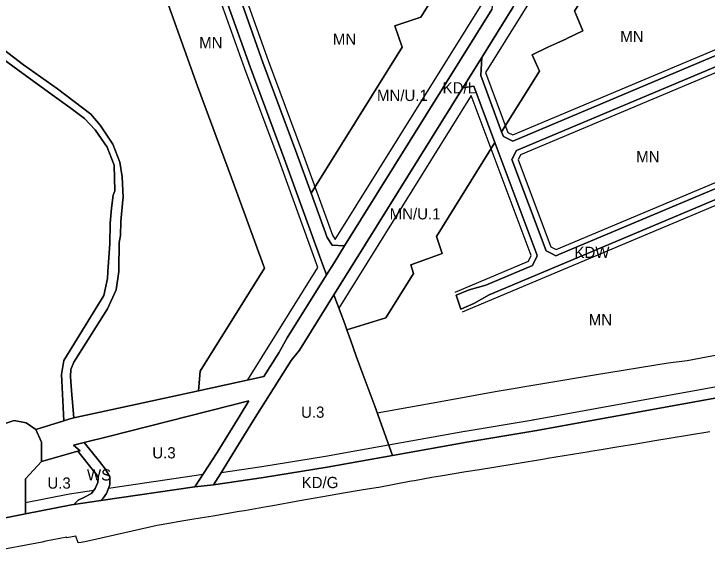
# Model space of a CAD drawing. Extents: x 7438199 to 7440548, y 5549253 to 5551017.
# Drawn here: x 7439598 to 7440215, y 5549324 to 5549804 of the extents above; entities that cross this region are included whole.
import ezdxf

# ---------------------------------------------------------------- set-up
doc = ezdxf.new("R2010")
doc.units = 0
for name, color, linetype in [('linie_rozgraniczajace', 7, 'Continuous'), ('linie_zabudowy_nieprzekraczalne', 7, 'Continuous'), ('oznaczenia_przeznaczen', 7, 'Continuous')]:
    doc.layers.add(name, color=color, linetype=linetype)

msp = doc.modelspace()

# ---------------------------------------------------------------- linework, layer by layer
at = {"layer": 'linie_rozgraniczajace'}
for points in [[(7440227.08, 5550005.17), (7440213.47, 5550001.07), (7440202.09, 5549996.27), (7440206.12, 5549984.95), (7440122.18, 5549849.49), (7440120.23, 5549848.95), (7440108.63, 5549844.06), (7440113.1, 5549832.93), (7440096.64, 5549806.47), (7440097.49, 5549804.44), (7440104.04, 5549788.87), (7440090.03, 5549782.03), (7440089.49, 5549781.67), (7440080.98, 5549777.82), (7440073.14, 5549774.28), (7440059.1, 5549767.45), (7440065.46, 5549752.89), (7440031.9, 5549698.99), (7440013.26, 5549748.91), (7440014.17, 5549765.09), (7440041.95, 5549809.72), (7440239.68, 5550128.82)], [(7439763.48, 5549881.63), (7439807.99, 5549756.65), (7439838.39, 5549675.06), (7439872.18, 5549581.79), (7439875.93, 5549571.43), (7439840.95, 5549515.24), (7439833.42, 5549501.96), (7439820.29, 5549480.94), (7439762.06, 5549468.22), (7439763.53, 5549485.48), (7439820.65, 5549577.24), (7439819.77, 5549579.67), (7439791.46, 5549657.81), (7439761.02, 5549739.54), (7439716.26, 5549865.2)], [(7439801.04, 5549811.94), (7439819.27, 5549760.76), (7439849.66, 5549679.19), (7439862.34, 5549644.19), (7439876.67, 5549604.63), (7439881.11, 5549597.9), (7439892.09, 5549597.4), (7439882.65, 5549582.22), (7439875.93, 5549571.43), (7439872.18, 5549581.79), (7439838.39, 5549675.06), (7439807.99, 5549756.65), (7439763.48, 5549881.63)], [(7439716.26, 5549865.2), (7439761.02, 5549739.54), (7439791.46, 5549657.81), (7439819.77, 5549579.67), (7439820.65, 5549577.24), (7439763.53, 5549485.48), (7439762.06, 5549468.22), (7439712.84, 5549457.46), (7439651.11, 5549443.98), (7439649.06, 5549468.02), (7439647.96, 5549480.76), (7439648.28, 5549487.18), (7439651.04, 5549493.78), (7439681.14, 5549541.18), (7439688.8, 5549557.97), (7439690.97, 5549574.44), (7439691.18, 5549576.06), (7439691.29, 5549600.29), (7439692.47, 5549606.39), (7439692.73, 5549619.01), (7439694.66, 5549638.27), (7439694.87, 5549640.3), (7439694.01, 5549658.77), (7439691.96, 5549671.97), (7439685.83, 5549687.74), (7439674.5, 5549704.91), (7439666.08, 5549714.5), (7439636.39, 5549737.26), (7439606.18, 5549758.61), (7439574.15, 5549782.83)], [(7440041.95, 5549809.72), (7440014.17, 5549765.09), (7439997.34, 5549738.06), (7439900.77, 5549582.95), (7439882.54, 5549553.67), (7439851.78, 5549504.26), (7439844.39, 5549495.21), (7439818.18, 5549453.4), (7439811.01, 5549441.98), (7439797.53, 5549420.26), (7439781.66, 5549394.3), (7439775.48, 5549384.28), (7439758.88, 5549382.65), (7439778.73, 5549413.02), (7439799.07, 5549446.3), (7439806.9, 5549459.11), (7439681.83, 5549427.53), (7439660.17, 5549422.14), (7439650.59, 5549419.75), (7439656.54, 5549414.79), (7439654.49, 5549414.36), (7439622.38, 5549405.09), (7439622.1, 5549422.44), (7439617.25, 5549433.53), (7439642.01, 5549441.52), (7439646.47, 5549442.96), (7439651.11, 5549443.98), (7439712.84, 5549457.46), (7439762.06, 5549468.22), (7439820.29, 5549480.94), (7439833.42, 5549501.96), (7439840.95, 5549515.24), (7439875.93, 5549571.43), (7439882.65, 5549582.22), (7439892.09, 5549597.4), (7440023.05, 5549807.75)], [(7439574.15, 5549782.83), (7439606.18, 5549758.61), (7439636.39, 5549737.26), (7439666.08, 5549714.5), (7439674.5, 5549704.91), (7439685.83, 5549687.74), (7439691.96, 5549671.97), (7439694.01, 5549658.77), (7439694.87, 5549640.3), (7439694.66, 5549638.27), (7439692.73, 5549619.01), (7439692.47, 5549606.39), (7439691.29, 5549600.29), (7439691.18, 5549576.06), (7439690.97, 5549574.44), (7439688.8, 5549557.97), (7439681.14, 5549541.18), (7439651.04, 5549493.78), (7439648.28, 5549487.18), (7439647.96, 5549480.76), (7439649.06, 5549468.02), (7439651.11, 5549443.98), (7439646.47, 5549442.96), (7439642.01, 5549441.52), (7439640.46, 5549476.93), (7439640.18, 5549482.55), (7439642.14, 5549495.24), (7439677.62, 5549553.11), (7439681.1, 5549568.15), (7439681.43, 5549574.05), (7439681.92, 5549582.88), (7439682.94, 5549599.17), (7439683.32, 5549617.61), (7439684.47, 5549630.97), (7439686.02, 5549642.49), (7439687.64, 5549646.31), (7439686.91, 5549669.24), (7439680.71, 5549685.04), (7439670.05, 5549700.55), (7439660.62, 5549710.78), (7439647.49, 5549720.45), (7439631.85, 5549731.72), (7439601.05, 5549753.98), (7439538.2, 5549800.16)], [(7439538.2, 5549800.16), (7439601.05, 5549753.98), (7439631.85, 5549731.72), (7439647.49, 5549720.45), (7439660.62, 5549710.78), (7439670.05, 5549700.55), (7439680.71, 5549685.04), (7439686.91, 5549669.24), (7439687.64, 5549646.31), (7439686.02, 5549642.49), (7439684.47, 5549630.97), (7439683.32, 5549617.61), (7439682.94, 5549599.17), (7439681.92, 5549582.88), (7439681.43, 5549574.05), (7439681.1, 5549568.15), (7439677.62, 5549553.11), (7439642.14, 5549495.24), (7439640.18, 5549482.55), (7439640.46, 5549476.93), (7439642.01, 5549441.52), (7439617.25, 5549433.53), (7439608.46, 5549439.62), (7439597.9, 5549441.69), (7439581.68, 5549436.46)], [(7440278.07, 5549662.09), (7440110.41, 5549591.46), (7440020.91, 5549553.76), (7440007.18, 5549545.81), (7439995.66, 5549540.95), (7439991.49, 5549553.3), (7440003.02, 5549558.16), (7440017.91, 5549562.26), (7440059.28, 5549579.69), (7440063.64, 5549588.25), (7440063.16, 5549589.54), (7440025.9, 5549689.34), (7440007.13, 5549739.6), (7439997.34, 5549738.06), (7440014.17, 5549765.09), (7440013.26, 5549748.91), (7440031.9, 5549698.99), (7440033.47, 5549694.77), (7440041.78, 5549690.58), (7440238.14, 5549773.3)], [(7440241.17, 5549764.81), (7440045.11, 5549682.22), (7440041.1, 5549674.34), (7440071.56, 5549592.77), (7440076.85, 5549590.1), (7440080.1, 5549588.46), (7440084.76, 5549590.42), (7440274.82, 5549670.48)], [(7440259.23, 5549468.33), (7440061.53, 5549432.46), (7440000.98, 5549422.24), (7439934.65, 5549410.37), (7439919, 5549454.41), (7439908.29, 5549483.06), (7439902.37, 5549499.13), (7439897.41, 5549513.68), (7439894.12, 5549522.48), (7439928.67, 5549533.17), (7439953.33, 5549572.78), (7439950.96, 5549580.21), (7439965.81, 5549585.59), (7439979, 5549590.38), (7439973.83, 5549605.7), (7440025.9, 5549689.34), (7440063.16, 5549589.54), (7440063.64, 5549588.25), (7440059.28, 5549579.69), (7440017.91, 5549562.26), (7440003.02, 5549558.16), (7439991.49, 5549553.3), (7439995.66, 5549540.95), (7440007.18, 5549545.81), (7440020.91, 5549553.76), (7440110.41, 5549591.46), (7440278.07, 5549662.09)], [(7439587.2, 5549354.42), (7439607.96, 5549358.49), (7439648.99, 5549366.53), (7439651.01, 5549366.83), (7439675.21, 5549370.38), (7439758.88, 5549382.65), (7439775.48, 5549384.28), (7439819.98, 5549390.82), (7439876.7, 5549400.05), (7439904.66, 5549405), (7439934.65, 5549410.37), (7440000.98, 5549422.24), (7440061.53, 5549432.46), (7440259.23, 5549468.33)], [(7439581.68, 5549436.46), (7439597.9, 5549441.69), (7439608.46, 5549439.62), (7439617.25, 5549433.53), (7439622.1, 5549422.44), (7439622.38, 5549405.09), (7439608.08, 5549389.85), (7439607.96, 5549358.49), (7439587.2, 5549354.42)], [(7440217.1, 5549431.57), (7440181.02, 5549425.58), (7440168.22, 5549423.45), (7440151.35, 5549420.69), (7440136.3, 5549418.22), (7440118.73, 5549415.33), (7440110.96, 5549414.12), (7440109.69, 5549413.84), (7440072.73, 5549407.78), (7440070.12, 5549407.35), (7440044.79, 5549403.19), (7440012.23, 5549397.84), (7439999.9, 5549395.81), (7439977.48, 5549392.21), (7439969.85, 5549390.99), (7439954.26, 5549388.05), (7439951.7, 5549387.57), (7439949.74, 5549387.2), (7439936.15, 5549384.64), (7439922.57, 5549382.07), (7439920.05, 5549381.65), (7439906.9, 5549379.47), (7439891.17, 5549376.85), (7439872.71, 5549373.77), (7439865.87, 5549372.55), (7439850.46, 5549369.77), (7439828.16, 5549365.74), (7439822.51, 5549364.72), (7439802.9, 5549361.31), (7439798.15, 5549360.49), (7439775.1, 5549356.49), (7439763.57, 5549354.59), (7439756.1, 5549353.35), (7439743.57, 5549351.28), (7439737.51, 5549350.28), (7439725.2, 5549348.24), (7439702.93, 5549343.16), (7439662.28, 5549333.88), (7439657.53, 5549333.09), (7439654.76, 5549332.63), (7439652.77, 5549338.73), (7439644.83, 5549337.21), (7439644.81, 5549337.61), (7439626.24, 5549334.05), (7439622.73, 5549333.39), (7439574.7, 5549324.39)]]:
    msp.add_lwpolyline(points, dxfattribs=at)
for points in [[(7439801.04, 5549811.94), (7439804.32, 5549817.04), (7439982.14, 5549876.05), (7439992.06, 5549879.34), (7440004.94, 5549873.39), (7439986.73, 5549844.01), (7439959.89, 5549800.9), (7439936.93, 5549793.24), (7439943.28, 5549774.21), (7439862.34, 5549644.19), (7439849.66, 5549679.19), (7439819.27, 5549760.76)], [(7439862.34, 5549644.19), (7439943.28, 5549774.21), (7439936.93, 5549793.24), (7439959.89, 5549800.9), (7439986.73, 5549844.01), (7440004.94, 5549873.39), (7440005.3, 5549873.22), (7440024.59, 5549825.51), (7440023.05, 5549807.75), (7439892.09, 5549597.4), (7439881.11, 5549597.9), (7439876.67, 5549604.63)], [(7440031.9, 5549698.99), (7440065.46, 5549752.89), (7440059.1, 5549767.45), (7440073.14, 5549774.28), (7440080.98, 5549777.82), (7440089.49, 5549781.67), (7440090.03, 5549782.03), (7440104.04, 5549788.87), (7440097.49, 5549804.44), (7440096.64, 5549806.47), (7440113.1, 5549832.93), (7440123.98, 5549837.51), (7440134.78, 5549843.69), (7440202.69, 5549872.29), (7440211.65, 5549868.35), (7440242.24, 5549782.61), (7440238.14, 5549773.3), (7440041.78, 5549690.58), (7440033.47, 5549694.77)], [(7440041.1, 5549674.34), (7440045.11, 5549682.22), (7440241.17, 5549764.81), (7440249.97, 5549760.93), (7440277.33, 5549684.23), (7440278.95, 5549679.86), (7440274.82, 5549670.48), (7440084.76, 5549590.42), (7440080.1, 5549588.46), (7440076.85, 5549590.1), (7440071.56, 5549592.77)], [(7439882.54, 5549553.67), (7439900.77, 5549582.95), (7439997.34, 5549738.06), (7440007.13, 5549739.6), (7440025.9, 5549689.34), (7439973.83, 5549605.7), (7439979, 5549590.38), (7439965.81, 5549585.59), (7439950.96, 5549580.21), (7439953.33, 5549572.78), (7439928.67, 5549533.17), (7439894.12, 5549522.48), (7439892.16, 5549527.73)], [(7439775.48, 5549384.28), (7439781.66, 5549394.3), (7439797.53, 5549420.26), (7439811.01, 5549441.98), (7439818.18, 5549453.4), (7439844.39, 5549495.21), (7439851.78, 5549504.26), (7439882.54, 5549553.67), (7439892.16, 5549527.73), (7439894.12, 5549522.48), (7439897.41, 5549513.68), (7439902.37, 5549499.13), (7439908.29, 5549483.06), (7439919, 5549454.41), (7439934.65, 5549410.37), (7439904.66, 5549405), (7439876.7, 5549400.05), (7439819.98, 5549390.82)], [(7439660.17, 5549422.14), (7439681.83, 5549427.53), (7439806.9, 5549459.11), (7439799.07, 5549446.3), (7439778.73, 5549413.02), (7439758.88, 5549382.65), (7439675.21, 5549370.38), (7439677.24, 5549372.37), (7439680.16, 5549376.78), (7439682.95, 5549384.34), (7439683.18, 5549391.58), (7439679.04, 5549398.48), (7439673.77, 5549405.06)], [(7439651.01, 5549366.83), (7439654.97, 5549370.64), (7439660.03, 5549372.93), (7439666.62, 5549376.59), (7439670.07, 5549381.14), (7439672.29, 5549386.41), (7439672.55, 5549390.35), (7439671.5, 5549393.22), (7439669.72, 5549395.42), (7439654.49, 5549414.36), (7439656.54, 5549414.79), (7439650.59, 5549419.75), (7439660.17, 5549422.14), (7439673.77, 5549405.06), (7439679.04, 5549398.48), (7439683.18, 5549391.58), (7439682.95, 5549384.34), (7439680.16, 5549376.78), (7439677.24, 5549372.37), (7439675.21, 5549370.38)], [(7439607.96, 5549358.49), (7439608.08, 5549389.85), (7439622.38, 5549405.09), (7439654.49, 5549414.36), (7439669.72, 5549395.42), (7439671.5, 5549393.22), (7439672.55, 5549390.35), (7439672.29, 5549386.41), (7439670.07, 5549381.14), (7439666.62, 5549376.59), (7439660.03, 5549372.93), (7439654.97, 5549370.64), (7439651.01, 5549366.83), (7439648.99, 5549366.53)]]:
    msp.add_lwpolyline(points, close=True, dxfattribs=at)
at = {"layer": 'linie_zabudowy_nieprzekraczalne'}
for points in [[(7440202.09, 5549996.27), (7440200.97, 5549999.6), (7440369.23, 5550070.48), (7440370.25, 5550073.06), (7440349.66, 5550118.04), (7440346.94, 5550119.43), (7440242.77, 5550114.82), (7440050.44, 5549804.44), (7440017.57, 5549751.65), (7440037.47, 5549698.35), (7440041.97, 5549696.09), (7440234.37, 5549777.13), (7440236.86, 5549782.8), (7440207.67, 5549864.64), (7440202.65, 5549866.85), (7440109.9, 5549827.78)], [(7439805.85, 5549477.79), (7439868.24, 5549577.99), (7439833.69, 5549673.35), (7439833.71, 5549673.31), (7439803.31, 5549754.91), (7439803.28, 5549754.98), (7439758.77, 5549879.95), (7439758.74, 5549880.02), (7439755.85, 5549888.52), (7439753.19, 5549897.17), (7439750.79, 5549905.9), (7439748.64, 5549914.69), (7439746.76, 5549923.54), (7439745.14, 5549932.37), (7439745.13, 5549932.45), (7439717.11, 5550099.56)], [(7439991.75, 5549873.98), (7439807.57, 5549812.86), (7439806.57, 5549811.3), (7439823.98, 5549762.44), (7439823.95, 5549762.51), (7439854.34, 5549680.94), (7439854.36, 5549680.9), (7439881.16, 5549606.89), (7439883.77, 5549602.95), (7440019.13, 5549820.36), (7440019.51, 5549824.75), (7440001.4, 5549869.52), (7439991.75, 5549873.98)], [(7440075.56, 5549596.35), (7440080.29, 5549593.96), (7440271.04, 5549674.32), (7440273.54, 5549679.99), (7440245.99, 5549757.23), (7440241.13, 5549759.37), (7440048.74, 5549678.33), (7440046.56, 5549674.03), (7440075.56, 5549596.35)], [(7439990.53, 5549556.15), (7440055.65, 5549583.59), (7440058.19, 5549588.56), (7440004.9, 5549731.29), (7439968.63, 5549673.04), (7439886.94, 5549541.81)], [(7440278.04, 5549656.65), (7439996.62, 5549538.1)], [(7439921.15, 5549448.36), (7439977.32, 5549458.54), (7440026.18, 5549467.58), (7440114.41, 5549482.29), (7440180.19, 5549492.99), (7440197.01, 5549495.27), (7440231.53, 5549501.54), (7440251.84, 5549505.69), (7440331.41, 5549519.67)], [(7439782.32, 5549395.39), (7439818.52, 5549400.71), (7439818.37, 5549400.69), (7439875.1, 5549409.92), (7439874.96, 5549409.9), (7439902.92, 5549414.85), (7439902.9, 5549414.85), (7439999.22, 5549432.08), (7439999.32, 5549432.1), (7440059.87, 5549442.32), (7440059.74, 5549442.3), (7440257.44, 5549478.17)], [(7439681.89, 5549381.47), (7439766.19, 5549393.83)], [(7439608, 5549368.69), (7439647.3, 5549376.39), (7439668.87, 5549379.56)]]:
    msp.add_lwpolyline(points, dxfattribs=at)

# ---------------------------------------------------------------- texts
at = {"layer": 'oznaczenia_przeznaczen'}
for s, p in [('MN', (7440137.45, 5549778.81)), ('MN', (7439762.6, 5549773.3)), ('MN', (7439881.62, 5549776.36)), ('KD/L', (7439979.31, 5549733.06)), ('MN/U.1', (7439920.9, 5549726.3)), ('MN', (7440151.69, 5549671.64)), ('MN/U.1', (7439932.17, 5549620.83)), ('KDW', (7440096.71, 5549586.46)), ('MN', (7440109.43, 5549526.53)), ('U.3', (7439853.29, 5549444.1)), ('U.3', (7439720.86, 5549407.89)), ('WS', (7439662.72, 5549388.22)), ('U.3', (7439627.48, 5549380.94)), ('KD/G', (7439853.83, 5549381.43))]:
    msp.add_text(s, height=10, dxfattribs=at).set_placement(p)

doc.saveas('drawing.dxf')
